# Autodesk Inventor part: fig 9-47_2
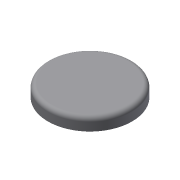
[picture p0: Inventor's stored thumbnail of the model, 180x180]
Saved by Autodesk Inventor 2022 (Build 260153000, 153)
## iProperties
Created: 2013-03
Part Number: fig 9-47_2
Material: Generic
Document SubType Name: Modeling
Designer: CADCIM
Density: 1 g/cm^3
Appearance: Default
Author: CADCIM
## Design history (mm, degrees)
sketch "Sketch1"
  geometry: C1 r 2.5 at (0, 0); 1 further point
  constraints: 1 centre point, 1 coincident
  dimensions: "d0" = 5 diameter of C1
extrude "Extrusion1" new body sketch "Sketch1" distance "d2" = 0.75; taper "d3" = 0 deg
fillet "Fillet1" dims "d4" = 0.25
body "Solid1"
